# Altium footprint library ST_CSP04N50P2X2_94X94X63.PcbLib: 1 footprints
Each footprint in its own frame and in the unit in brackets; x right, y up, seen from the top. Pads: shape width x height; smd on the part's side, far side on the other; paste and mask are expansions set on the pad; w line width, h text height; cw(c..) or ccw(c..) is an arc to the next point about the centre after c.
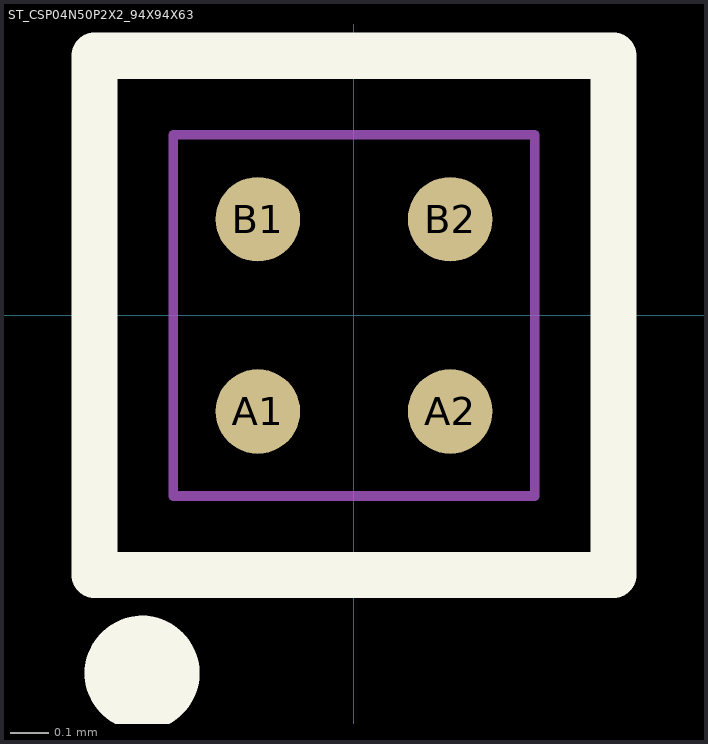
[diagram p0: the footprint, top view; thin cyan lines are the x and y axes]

## ST_CSP04N50P2X2_94X94X63 [mm] "ST_CSP04N50P2X2_94X94X63"
pads (4):
  round 0.22 smd mask+0.05: A1(-0.25,-0.25) A2(0.25,-0.25) B1(-0.25,0.25) B2(0.25,0.25)
Top Overlay:
  circle w0.2: c-0.551,-0.931 r0.049
  lines w0.12: -0.675,-0.675 0.675,-0.675 0.675,0.675 -0.675,0.675 -0.675,-0.675
Top Paste:
  rectangle: 0.14,-0.36 0.36,-0.14
  rectangle: 0.14,0.14 0.36,0.36
  rectangle: -0.36,0.14 -0.14,0.36
  rectangle: -0.36,-0.36 -0.14,-0.14
Mechanical 5:
  text "A1" at -0.31,-0.7 h0.1
  text "B2" at 0.19,0.6 h0.1
  text "A2" at 0.19,-0.7 h0.1
  text "B1" at -0.36,0.6 h0.1
Mechanical 6:
  lines w0.025: -0.47,-0.47 -0.47,0.47 0.47,0.47 0.47,-0.47 -0.47,-0.47
Mechanical 7:
  lines w0.025: -0.47,-0.47 0.47,-0.47 0.47,0.47 -0.47,0.47 -0.47,-0.47
3D body: height 0.63, standoff 0.21, extent -0.47,-0.47 0.47,0.47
